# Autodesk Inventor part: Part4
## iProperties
Created: 2002-04
Part Number: Part4
Document SubType Name: Sheet Metal
Control State: 0
Master: False
Checked Out: False
Shininess: 77.0
Angle Display Precision: 2
Document Length Units: 11269
Document Angle Units: 11279
Document Time Units: 11290
Document Mass Units: 11283
Document Length Units Precision: 3
Document Angle Units Precision: 2
Compacted: True
Density: 0.0
Volumn: 0.0
Area: 0.0
PropertySet Name: Model Information
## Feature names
1. Extrusion1
2. Shell1
